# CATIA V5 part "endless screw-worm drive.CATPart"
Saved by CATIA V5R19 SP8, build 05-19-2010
Part number: endless screw-worm drive
Bounding box of the stored display mesh (mm): x -4.5 to 4.5, y 115.1 to 152.1, z -4.5 to 4.5
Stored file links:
  G:\EU_thinkMotion\CFAO_2010\MMS_groupe1\MMS_groupe1\A reprendre\gduval\CFAO kinematic ok\endless screw-worm drive.CATPart
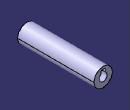
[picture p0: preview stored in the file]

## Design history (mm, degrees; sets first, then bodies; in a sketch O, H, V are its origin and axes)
Body1 (main body)
  Plane1 to Plane3: stored without definition
  Point1: stored without definition
  Line1: type Normal, RefPoint Point1, RefSkin Plane1, Start -20, End 20
  Sketch1 on Plane1, origin (0, 130.1, 0), H (-1, 0, 0), V (0, 0, 1)
    circle A1 centre (0, 0) radius 4.5
    radius A1 = 4.5
  Pad1: profile Sketch1, direction (0, 1, 0), up to Plane3, opposite side length 15
  Sketch2 on end face of Pad1, origin (0, 152.1, 0), H (-1, 0, 0), V (0, 0, 1)
    arc A1 centre (0, 0) radius 2 from (-1, 1.7321) to (1, 1.7321) ccw
    point P2 (1, 1.7321)
    line L1 (-1, 1.7321) -> (-1, 3.2321)
    point P3 (-1, 3.2321)
    line L2 (1, 1.7321) -> (1, 3.2321)
    point P4 (1, 1.7321)
    axis line L3 (0, 0) -> (0, 2.8139)
    line L4 (1, 3.2321) -> (-1, 3.2321)
    point P7 (-1, 3.2321)
    distance L2 L3 = 1
    distance L3 L1 = 1
    radius A1 = 2
    length L2 = 1.5
    parallelism: L1 L2
    coincidence: P4 P2, P7 P3
    vertical: L3 V
    horizontal: L4 H
  Pocket1: profile Sketch2, direction (0, -1, 0), through (limit type 6)
  Plane4: type OffsetPt, RefPlane xy-plane, RefPoint Point1
  Line2: type Normal, RefPoint Point1, RefSkin Plane4, Start -20, End 20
